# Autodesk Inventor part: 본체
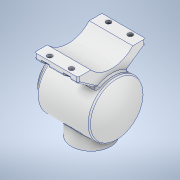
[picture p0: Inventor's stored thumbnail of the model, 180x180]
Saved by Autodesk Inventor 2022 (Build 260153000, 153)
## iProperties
Created: 2023-04
Part Number: 본체
Material: 알루미늄 6061
Document SubType Name: Modeling
Designer: Admin
Mass: 1296.69 g
Surface Area: 1060.44 cm^2
Volume: 480.256 cm^3
Density: 2.7 g/cm^3
Appearance: 알루미늄 - 평지
Author: Admin
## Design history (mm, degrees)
sketch "스케치1"
  geometry: L1 (-84.575, 0)-(87.453, 0) reference; L2 (0, -10.134)-(0, 60.805) reference; L3 (-60, 0)-(-60, 36); L4 (-60, 36)-(-48, 36); L5 (-48, 36)-(-48, 50); L6 (-48, 50)-(48.336, 50); L7 (-60, 0)-(60, 0); A1 r 113 centre (-53, 0) between (60, 0) and (48.336, 50); 1 further point
  constraints: 10 end point, 3 perpendicular, 3 point on line, 2 point on circle, 1 centre point, 1 collinear, 1 symmetric about line, 1 vertical
  dimensions: "d0" = 113 radius of A1; "d1" = 100 diameter of L6 L1; "d2" = 72 diameter of L4 L1; "d3" = 120 distance from line of L7.end L3; "d4" = 108 distance from line of L7.end L5
revolve "회전1" sketch "스케치1" stored, may be unused: angle "d5" = 90 deg
node "작업 평면1"
sketch "스케치2"
  geometry: L1 (80, 0)-(-60, 0) reference; L2 (0, -86.8)-(0, 86.8) reference; L3 (60, 36)-(60, -36) reference; C1 r 36 at (-2, 0); 1 further point
  constraints: 1 centre point, 1 point on line
  dimensions: "d7" = 72 diameter of C1; "d8" = 62 distance from line of L3 C1.centre
extrude "돌출1" join sketch "스케치2" stored distance "d9" = 10; taper "d10" = 0 deg
sketch "스케치3"
  geometry: L1 (-75.4, 0)-(102.4, 0) reference; L2 (0, -86.8)-(0, 86.8) reference; L3 (42.278, 26.694)-(67, 62); L4 (67, 62)-(77, 62); L5 (77, 62)-(77, -62); L6 (77, -62)-(67, -62); L7 (67, -62)-(42.278, -26.694); C1 r 50 at (0, 0); A1 r 50 centre (0, 0) between (42.278, 26.694) and (42.278, -26.694) reference; 4 further points
  constraints: 10 end point, 2 perpendicular, 1 centre point, 1 coincident, 1 concentric, 1 horizontal, 1 point on circle, 3 other
  dimensions: "d11" = 10 distance of L5.end L6.end; "d12" = 55 deg angle of L6 L7; "d13" = 77 distance between parallel lines of L5 L2; "d14" = 10 distance of L3.end L4.end; "d15" = 55 deg angle of L4 L3; "d16" = 124 distance of L4.end L5.end
extrude "돌출2" join sketch "스케치3" stored distance "d17" = 80; taper "d18" = 0 deg
sketch "스케치4"
  geometry: L1 (62, 77)-(-62, 77) reference; L2 (-62, 77)-(-62, 67) reference; L3 (-62, 67)-(-26.694, 42.278) reference; L4 (26.694, 42.278)-(62, 67) reference; L5 (62, 67)-(62, 77) reference; L6 (0, -100.419)-(0, 147.515) reference; L7 (-86.8, 0)-(86.8, 0) reference; L8 (-62, 77)-(62, 77) reference; L9 (38.5, 77)-(-38.5, 77); L10 (0, 60)-(-28, 60); A1 r 50 centre (0, 0) between (26.694, 42.278) and (-26.694, 42.278) reference; A2 r 52.096 centre (0, 112.096) between (-38.5, 77) and (38.5, 77); 1 further point
  constraints: 4 end point, 3 point on circle, 3 point on line, 1 centre point, 1 horizontal
  dimensions: "d19" = 77 distance of L9.end L9.start; "d20" = 17 distance between parallel lines of L1 L10
extrude "돌출3" cut sketch "스케치4" extent not by distance; stored distance "d21" = 0; taper "d22" = 0 deg
sketch "스케치5"
  geometry: L1 (-84, 0)-(84, 0) reference; L2 (0, -70)-(0, 70) reference; L3 (-60, -36)-(-60, 36) reference; L4 (-60, -27)-(-41, -27); L5 (-41, -27)-(-41, -43); L6 (-41, -43)-(43.887, -43); L7 (-60, -27)-(-60, 0); L8 (-60, 0)-(53, 0); A1 r 113 centre (-53, 0) between (48.336, -50) and (48.336, 50) reference; A2 r 106 centre (-53, 0) between (43.887, -43) and (53, 0); 1 further point
  constraints: 10 end point, 2 point on circle, 2 point on line, 1 centre point, 1 collinear, 1 horizontal, 1 midpoint, 1 perpendicular, 1 vertical
  dimensions: "d23" = 7 radial gap between concentric circles of A1 A2; "d24" = 86 diameter of L6 L1; "d25" = 54 diameter of L4 L1; "d26" = 19 distance of L4.start L4.end
revolve "회전2" sketch "스케치5" stored, may be unused: angle "d27" = 90 deg
sketch "스케치6"
  geometry: C1 r 36 at (0, 0) reference; C2 r 27 at (0, 0); 1 further point
  constraints: 1 centre point, 1 coincident
  dimensions: "d28" = 54 diameter of C2
extrude "돌출4" cut sketch "스케치6" stored distance "d29" = 10; taper "d30" = 0 deg
sketch "스케치7" dims "d31" = 65
  geometry: L1 (-86, 0)-(82, 0) reference; L2 (-2, -86.8)-(-2, 86.8) reference; C1 r 36 at (0, 0) reference; C2 r 27 at (0, 0) reference; C3 r 27 at (0, 0) reference; C4 r 36 at (0, 0) reference; 3 further points
  constraints: 1 coincident, 1 horizontal alignment, 1 point on line, 2 other
hole "구멍1" sketch "스케치7" at (32.5, 0) diameter "d32" = 3.242; stored, may be unused: countersink angle "d36" = 90 deg, drill point angle "d38" = 118 deg; dims "d33" = 8, "d34" = 4, "d35" = 2, "d37" = 10
node "작업 평면2"
sketch "스케치8"
  geometry: L1 (60, 36)-(60, -36) reference; L2 (80, 0)-(-60, 0) reference; L3 (0, -51.2)-(0, 55.2) reference; 2 further points
  constraints: 1 point on line, 1 other
  dimensions: "d45" = 62 distance from line of L1 point (-2, 0)
feature "엠보싱1" sketch "스케치8" dims "d0" = 113, "d1" = 100, "d2" = 72, "d3" = 120, "d4" = 108, "d43" = 0.5, "d44" = 0
node "작업 평면3"
sketch "스케치10"
  geometry: L1 (40, -26.694)-(-40, -26.694) reference; L2 (40, -62)-(40, -26.694) reference; L3 (40, -62)-(-40, -62) reference; L4 (-40, -26.694)-(-40, -62) reference; L5 (-40, 26.694)-(40, 26.694) reference; L6 (-40, 62)-(-40, 26.694) reference; L7 (40, 62)-(-40, 62) reference; L8 (40, 26.694)-(40, 62) reference; L9 (56, 0)-(-56, 0) reference; L10 (0, -86.8)-(0, 86.8) reference; L11 (-40, -62)-(40, -62) reference; L12 (-27, -62)-(-13, -62); L13 (-13, -62)-(-13, -54); L14 (-27, -54)-(-27, -62); L15 (13, -62)-(27, -62); L16 (27, -62)-(27, -54); L17 (13, -54)-(13, -62); A1 r 7 centre (20, -54) between (27, -54) and (13, -54); A2 r 7 centre (-20, -54) between (-13, -54) and (-27, -54); 1 further point
  constraints: 12 end point, 4 point on circle, 4 tangent, 2 centre point, 2 horizontal, 2 parallel, 2 perpendicular, 2 point on line
  dimensions: "d47" = 20 distance from line of L4 A2.centre; "d48" = 40 distance of A1.centre A2.centre; "d49" = 8 distance from line of L3 A2.centre; "d50" = 14 distance between parallel lines of L14 L13; "d51" = 14 distance between parallel lines of L16 L17; "d52" = 8 distance from line of L3 A1.centre
extrude "돌출5" cut sketch "스케치10" distance "d53" = 31; taper "d54" = 0 deg
sketch "스케치11"
  geometry: L1 (-40, -38.5)-(40, -38.5) reference; L2 (40, -62)-(40, -38.5) reference; L3 (40, -62)-(-40, -62) reference; L4 (-40, -38.5)-(-40, -62) reference; L5 (-13, -62)-(13, -62) reference; L6 (-13, -62)-(-27, -62) reference; L7 (-40, -62)-(-27, -62) reference; L8 (40, -62)-(-40, -62) reference; L9 (27, -62)-(40, -62) reference; L10 (27, -62)-(13, -62) reference; C1 r 4.5 at (-20, -54); C2 r 4.5 at (20, -54); 1 further point
  constraints: 2 centre point
  dimensions: "d55" = 9 diameter of C1; "d56" = 9 diameter of C2; "d57" = 20 distance from line of L4 C1.centre; "d58" = 40 distance of C2.centre C1.centre; "d59" = 8 distance from line of L3 C1.centre; "d60" = 8 distance from line of L10 C2.centre
extrude "돌출6" cut sketch "스케치11" extent not by distance; stored distance "d61" = 0; taper "d62" = 0 deg
sketch "스케치12"
  geometry: L1 (0, -93.4)-(0, 105.4) reference; L2 (-86.8, 0)-(86.8, 0) reference; C1 r 36 at (0, 0) reference; C2 r 27 at (0, 0) reference; A1 r 32.5 centre (0, 0) between (0, -32.5) and (-32.5, 0); 3 further points
  constraints: 4 point on circle, 4 point on line, 1 centre point, 1 coincident
  dimensions: "d63" = 65 diameter of A1
hole "구멍2" sketch "스케치12" at (0, -32.5), (-32.5, 0), (0, 32.5), (32.5, 0) diameter "d64" = 3.242; stored, may be unused: countersink angle "d68" = 90 deg, drill point angle "d70" = 118 deg; dims "d65" = 8, "d66" = 4, "d67" = 2, "d69" = 10
chamfer "모따기1" distance "d71" = 1; stored, may be unused: second distance "d72" = 2, angle "d73" = 45 deg
fillet "모깎기1" dims "d74" = 3
fillet "모깎기2" dims "d75" = 3
node "솔리드1"
pattern_circular "원형 패턴1" dims angle "d40" = 360 deg
mirror "미러1"
node "투영된 루프1"
node "투영된 루프2"
node "투영된 루프3"
node "투영된 루프6"
node "투영된 루프7"
node "투영된 루프8"
node "투영된 루프9"
feature "A9D066F2-1C7D-4E18-AEED-F7BC21143FA4" dims "d32" = 3.242, "d33" = 8, "d34" = 4, "d35" = 2, "d36" = 90 deg, "d37" = 10, "d38" = 118 deg
other parameters: "d6" = -65, "d42" = -83
